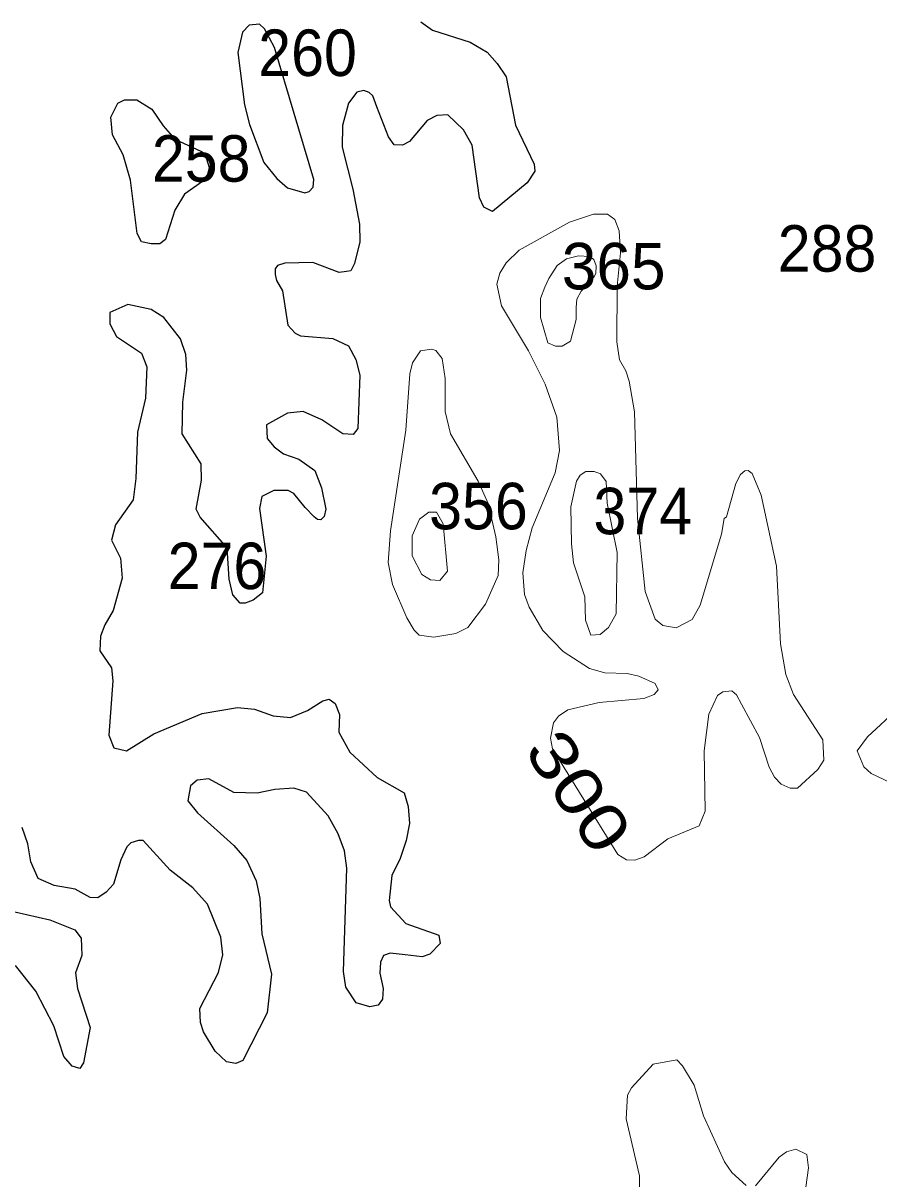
# Model space of a CAD drawing. Extents: x 499.9 to 555.3, y 9281.5 to 9336.8.
# Drawn here: x 506.421 to 509.363, y 9328.05 to 9332.026 of the extents above; entities that cross this region are included whole.
import ezdxf
from ezdxf.enums import TextEntityAlignment as Align

# ---------------------------------------------------------------- set-up
doc = ezdxf.new("R2010")
doc.units = 0
doc.header["$LTSCALE"] = 0.064
doc.layers.add('1', color=7, linetype='Continuous', lineweight=25)
doc.layers.add('2', color=7, linetype='Continuous', lineweight=13)
doc.layers.add('21', color=7, linetype='Continuous')
doc.layers.add('61', color=7, linetype='Continuous')

msp = doc.modelspace()

# ---------------------------------------------------------------- linework, layer by layer
at = {"layer": '1'}
for points in [[(507.7881, 9332.0308), (507.8282, 9332.0016), (507.9578, 9331.9605), (508.0161, 9331.9264), (508.051, 9331.8873), (508.081, 9331.8411), (508.1132, 9331.6757), (508.1773, 9331.5408), (508.1797, 9331.5171), (508.1537, 9331.4762), (508.034, 9331.3778), (508.0051, 9331.3926), (507.9893, 9331.4251), (507.9646, 9331.6063), (507.9352, 9331.659), (507.8806, 9331.7103), (507.8426, 9331.7082), (507.8102, 9331.6909), (507.7485, 9331.6185), (507.7247, 9331.6059), (507.6969, 9331.6072), (507.6766, 9331.635), (507.6373, 9331.7378), (507.6232, 9331.7763), (507.6099, 9331.787), (507.5922, 9331.7941), (507.5685, 9331.7882), (507.5397, 9331.7505), (507.5187, 9331.6741), (507.5175, 9331.5999), (507.5546, 9331.4552), (507.5767, 9331.3342), (507.5781, 9331.2738), (507.5602, 9331.1995), (507.5477, 9331.1744), (507.5323, 9331.1721), (507.5068, 9331.1682), (507.4168, 9331.2026), (507.32, 9331.2007), (507.2955, 9331.1928), (507.2875, 9331.1809), (507.2869, 9331.1616), (507.2922, 9331.1411), (507.3124, 9331.1057), (507.3307, 9330.9872), (507.3565, 9330.9601), (507.3747, 9330.95), (507.486, 9330.9417), (507.5398, 9330.9157), (507.5642, 9330.8695), (507.5783, 9330.8154), (507.5717, 9330.6317), (507.5558, 9330.611), (507.5204, 9330.613), (507.4478, 9330.6617), (507.3833, 9330.6902), (507.3301, 9330.684), (507.2576, 9330.6446), (507.26, 9330.5971), (507.2839, 9330.568), (507.3158, 9330.5442), (507.3689, 9330.526), (507.4241, 9330.4874), (507.4462, 9330.4278), (507.4619, 9330.3537), (507.4552, 9330.3288), (507.4438, 9330.3174), (507.4323, 9330.3187), (507.4213, 9330.328), (507.3906, 9330.3595), (507.3512, 9330.408), (507.3322, 9330.4179), (507.2824, 9330.4181), (507.2417, 9330.3978), (507.2331, 9330.3559), (507.2568, 9330.1923), (507.2434, 9330.0661), (507.2122, 9330.0413), (507.1843, 9330.0303), (507.1673, 9330.0307), (507.1418, 9330.059), (507.1296, 9330.1135), (507.1225, 9330.2215), (507.0299, 9330.3269), (507.0154, 9330.354), (507.0339, 9330.4534), (507.0323, 9330.5098)], [(506.9623, 9330.9402), (506.9047, 9331.0139), (506.8613, 9331.0408), (506.7808, 9331.0581), (506.7192, 9331.0301), (506.7192, 9330.9914), (506.7413, 9330.9484), (506.8278, 9330.8908), (506.8462, 9330.844), (506.8412, 9330.7358), (506.8136, 9330.6186), (506.808, 9330.4597), (506.7986, 9330.3862), (506.7385, 9330.2996), (506.7242, 9330.2473), (506.7554, 9330.1849), (506.7617, 9330.1162), (506.7306, 9330.0059), (506.7013, 9329.9559), (506.6867, 9329.9172), (506.6841, 9329.8667), (506.7247, 9329.8077), (506.7297, 9329.7629), (506.716, 9329.5765), (506.733, 9329.5326), (506.7761, 9329.5227), (506.8701, 9329.5811), (507.0365, 9329.6508), (507.1573, 9329.6717), (507.2166, 9329.6657), (507.28, 9329.6432), (507.3396, 9329.6371), (507.3985, 9329.6608), (507.4509, 9329.6945), (507.4733, 9329.7001), (507.4937, 9329.6859), (507.5082, 9329.6472), (507.5056, 9329.5868), (507.5434, 9329.5176), (507.6381, 9329.4305), (507.7303, 9329.3776), (507.7449, 9329.3315), (507.7485, 9329.2724), (507.7379, 9329.2139), (507.7171, 9329.1522), (507.6881, 9329.0933), (507.6788, 9329.0079), (507.6834, 9328.986), (507.7367, 9328.9285), (507.8497, 9328.8889), (507.8546, 9328.8602), (507.8192, 9328.8226), (507.7923, 9328.8143), (507.7343, 9328.8203), (507.6822, 9328.8264), (507.6599, 9328.8183), (507.6496, 9328.7952), (507.6467, 9328.7578), (507.6591, 9328.7051), (507.6563, 9328.6682), (507.6414, 9328.6475), (507.6125, 9328.6423), (507.5653, 9328.656), (507.5307, 9328.709), (507.5227, 9328.7632), (507.5335, 9329.1185), (507.5251, 9329.1789), (507.5035, 9329.2374), (507.4695, 9329.2984), (507.3952, 9329.3804), (507.3515, 9329.3946), (507.2856, 9329.3901), (507.225, 9329.3775), (507.1455, 9329.379), (507.0595, 9329.4265), (507.0195, 9329.4215), (506.9961, 9329.4026), (506.9875, 9329.3504), (507.0197, 9329.3091), (507.1448, 9329.1965), (507.1894, 9329.1456), (507.2217, 9329.075), (507.2345, 9329.0145), (507.2412, 9328.8928), (507.2742, 9328.7542), (507.2595, 9328.6208), (507.1757, 9328.4569), (507.1517, 9328.4466), (507.1203, 9328.4522), (507.0806, 9328.4897), (507.0408, 9328.5554), (507.0301, 9328.5883), (507.0281, 9328.6364), (507.0928, 9328.76), (507.1071, 9328.8213)], [(507.0323, 9330.5098), (506.9674, 9330.6134), (506.9702, 9330.722), (506.9831, 9330.8321), (506.9798, 9330.8862), (506.9623, 9330.9402)], [(506.8338, 9329.2139), (506.8174, 9329.2146), (506.7913, 9329.2057), (506.7779, 9329.1927), (506.7568, 9329.1474), (506.7314, 9329.064), (506.7066, 9329.0359), (506.6774, 9329.0171), (506.6513, 9329.0183), (506.6002, 9329.0464), (506.5272, 9329.0595), (506.4721, 9329.0839), (506.4471, 9329.1412), (506.4369, 9329.2031), (506.4171, 9329.2591)], [(507.1071, 9328.8213), (507.1005, 9328.8816), (507.0547, 9328.9948), (507.0037, 9329.0512), (506.9268, 9329.1122), (506.8338, 9329.2139)], [(506.3918, 9328.9683), (506.5128, 9328.941), (506.599, 9328.9065), (506.6198, 9328.8782), (506.6229, 9328.8179), (506.6013, 9328.7584), (506.6073, 9328.7046), (506.6517, 9328.5713), (506.6289, 9328.4495), (506.6152, 9328.4292), (506.5893, 9328.4372), (506.5609, 9328.471), (506.5263, 9328.576), (506.4642, 9328.6962), (506.3946, 9328.7846)]]:
    msp.add_lwpolyline(points, dxfattribs=at)
for points in [[(507.2853, 9331.9427), (507.2508, 9332.0069), (507.2329, 9332.0232), (507.1981, 9332.0191), (507.1755, 9331.9946), (507.1585, 9331.9252), (507.1815, 9331.7455), (507.1987, 9331.6776), (507.2481, 9331.5471), (507.2929, 9331.4917), (507.3295, 9331.4599), (507.3895, 9331.4422), (507.4047, 9331.4467), (507.4182, 9331.4613), (507.4206, 9331.4882)], [(506.8612, 9331.2667), (506.8277, 9331.2733), (506.8128, 9331.3028), (506.7901, 9331.486), (506.7642, 9331.573), (506.7285, 9331.6415), (506.7229, 9331.7028), (506.7467, 9331.7503), (506.7693, 9331.7628), (506.8112, 9331.7628), (506.863, 9331.7301), (506.902, 9331.6725), (506.9428, 9331.627), (507.0337, 9331.5846), (507.0515, 9331.5597), (507.0604, 9331.53), (507.0546, 9331.5056), (507.037, 9331.4816), (506.9759, 9331.4374), (506.9428, 9331.3826), (506.91, 9331.282), (506.8909, 9331.2669)]]:
    msp.add_lwpolyline(points, close=True, dxfattribs=at)
at = {"layer": '2'}
for points in [[(508.7486, 9330.0243), (508.8214, 9330.2679), (508.8313, 9330.3221), (508.8391, 9330.3278), (508.8712, 9330.4427), (508.8874, 9330.4729), (508.9014, 9330.4857), (508.9132, 9330.4872), (508.9265, 9330.4763), (508.9582, 9330.4024), (509.0105, 9330.1581), (509.025, 9329.8907), (509.0433, 9329.7851), (509.0689, 9329.7165), (509.17, 9329.5604), (509.173, 9329.4901), (509.1533, 9329.4581), (509.0825, 9329.3938), (509.0579, 9329.3937), (509.027, 9329.4074), (509.0042, 9329.432), (508.9853, 9329.4666), (508.9518, 9329.5684), (508.8901, 9329.6835), (508.8729, 9329.7156), (508.8571, 9329.7288), (508.8264, 9329.7257), (508.8084, 9329.7125), (508.778, 9329.6484), (508.7626, 9329.5224), (508.7657, 9329.3154), (508.745, 9329.2651), (508.6377, 9329.2194), (508.5555, 9329.158), (508.5237, 9329.1468), (508.4948, 9329.1481), (508.4654, 9329.166), (508.3332, 9329.3791), (508.2402, 9329.529), (508.2342, 9329.566), (508.2436, 9329.6186), (508.2618, 9329.642), (508.293, 9329.6638), (508.401, 9329.6891), (508.5547, 9329.7021), (508.5904, 9329.7166), (508.6043, 9329.7324), (508.5941, 9329.7537), (508.5372, 9329.7798), (508.4975, 9329.7881), (508.4211, 9329.7915), (508.3684, 9329.8054), (508.2771, 9329.8641), (508.207, 9329.9361), (508.1608, 9330.0174), (508.1447, 9330.0603), (508.1386, 9330.135), (508.1498, 9330.2122), (508.171, 9330.2895), (508.2499, 9330.4788), (508.2642, 9330.5553), (508.256, 9330.6706), (508.2151, 9330.7837), (508.1576, 9330.8989), (508.0656, 9331.0541), (508.0498, 9331.128), (508.0592, 9331.1663), (508.081, 9331.2016), (508.1255, 9331.2454), (508.2994, 9331.3414), (508.3813, 9331.3685), (508.4293, 9331.3685), (508.4551, 9331.3507), (508.4696, 9331.3121), (508.4743, 9331.2364), (508.4632, 9331.1208), (508.4617, 9330.9303), (508.4712, 9330.8673), (508.493, 9330.8296), (508.5046, 9330.7939), (508.5221, 9330.6889), (508.5333, 9330.3228), (508.5593, 9330.0706), (508.5935, 9329.9752), (508.6195, 9329.9533), (508.6661, 9329.9459), (508.721, 9329.9746)], [(508.3029, 9330.9318), (508.3223, 9331.0063), (508.3215, 9331.0474), (508.3247, 9331.0766), (508.3397, 9331.1035), (508.383, 9331.1524), (508.3901, 9331.1644), (508.3906, 9331.1915), (508.3831, 9331.2133), (508.3684, 9331.2234), (508.3302, 9331.2252), (508.289, 9331.2157), (508.2571, 9331.1921), (508.2279, 9331.1471), (508.214, 9331.1177), (508.1998, 9331.079), (508.1994, 9331.0139), (508.2251, 9330.9263), (508.2509, 9330.9152), (508.2739, 9330.9149)], [(507.6835, 9330.28), (507.7361, 9330.6257), (507.7504, 9330.8202), (507.7599, 9330.8575), (507.7873, 9330.8986), (507.8247, 9330.9049), (507.8398, 9330.8999), (507.8616, 9330.8726), (507.8711, 9330.8035), (507.8711, 9330.6897), (507.8901, 9330.6128), (507.9854, 9330.4508), (508.0191, 9330.3737), (508.0463, 9330.2584), (508.0557, 9330.1796), (508.054, 9330.1254), (508.01, 9330.0275), (507.9498, 9329.9469), (507.9087, 9329.9264), (507.833, 9329.9138), (507.7827, 9329.9201), (507.7646, 9329.9378), (507.7398, 9329.9806), (507.6909, 9330.0953), (507.6755, 9330.1701)], [(508.4629, 9330.2046), (508.4281, 9330.3743), (508.4251, 9330.4488), (508.4054, 9330.4756), (508.3836, 9330.4833), (508.3558, 9330.4834), (508.336, 9330.4707), (508.3229, 9330.4509), (508.3041, 9330.3617), (508.3057, 9330.2349), (508.3131, 9330.169), (508.3517, 9330.0522), (508.3542, 9329.9727), (508.3725, 9329.9209), (508.4049, 9329.9234), (508.4333, 9329.9464), (508.4596, 9329.9945)], [(507.7586, 9330.1935), (507.7587, 9330.2628), (507.7837, 9330.3194), (507.816, 9330.3439), (507.8422, 9330.344), (507.8653, 9330.3034), (507.8799, 9330.1402), (507.8535, 9330.1084), (507.8211, 9330.1109), (507.7912, 9330.1296)]]:
    msp.add_lwpolyline(points, close=True, dxfattribs=at)
for points in [[(509.4303, 9329.6697), (509.3231, 9329.5705), (509.288, 9329.5222), (509.3113, 9329.4673), (509.3366, 9329.4448), (509.4882, 9329.3726)], [(508.9061, 9328.0273), (508.8569, 9328.0718), (508.8325, 9328.1086), (508.7603, 9328.2669), (508.7271, 9328.3722), (508.6872, 9328.439), (508.6684, 9328.4591), (508.5869, 9328.4442), (508.512, 9328.3633), (508.4984, 9328.3374), (508.4936, 9328.2563), (508.5394, 9328.0603), (508.5395, 9328.0047)], [(509.1066, 9327.9881), (509.1203, 9328.0875), (509.1154, 9328.1341), (509.0776, 9328.1516), (509.0452, 9328.1434), (509.0198, 9328.1242), (508.9385, 9328.0259)]]:
    msp.add_lwpolyline(points, dxfattribs=at)

# ---------------------------------------------------------------- texts
at = {"layer": '21', "width": 0.95}
for s, p in [('260', (507.229, 9331.8443)), ('258', (506.8634, 9331.4807)), ('288', (509.0149, 9331.1711)), ('356', (507.8165, 9330.2847)), ('374', (508.3814, 9330.2677)), ('276', (506.9177, 9330.0788))]:
    msp.add_text(s, height=0.16, dxfattribs=at).set_placement(p)
at = {"layer": '21'}
msp.add_text('365', height=0.16, dxfattribs=at).set_placement((508.2724, 9331.1103))
at = {"layer": '61', "width": 1.25}
msp.add_text('300', height=0.16, rotation=303.907, dxfattribs=at).set_placement((508.2643, 9329.3382), align=Align.CENTER)

doc.saveas('drawing.dxf')
